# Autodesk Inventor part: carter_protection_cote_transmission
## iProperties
Created: 2011-01
Part Number: carter_protection_cote_transmission
Document SubType Name: Modeling
Designer: eric
Density: 1 g/cm^3
Mass: 31.8154 g
Surface Area: 355.166 cm^2
Volume: 31.8154 cm^3
Author: eric
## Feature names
1. Base1
